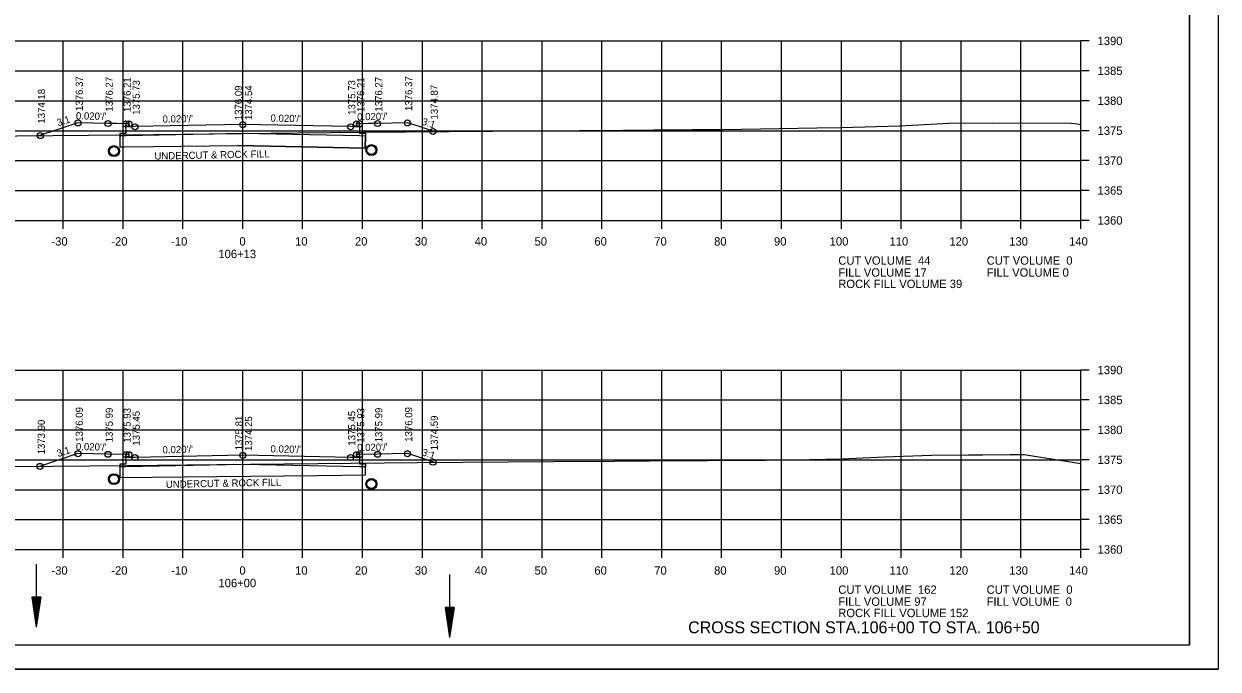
# Model space of a CAD drawing. Extents: x 1374311 to 1383814, y 384102 to 406278.
# Drawn here: x 1382684.3 to 1382883.8, y 385759.2 to 385867.1 of the extents above; entities that cross this region are included whole.
import ezdxf

# ---------------------------------------------------------------- set-up
doc = ezdxf.new("R2010")
doc.units = 0
for name, color, linetype in [('R_Axis', 7, 'Continuous'), ('R_Axis Annot', 7, 'Continuous'), ('R_Border', 7, 'Continuous'), ('R_Draft', 7, 'Continuous'), ('R_Exist Surface', 7, 'Continuous'), ('R_Fin Surface', 7, 'Continuous'), ('R_Grid', 7, 'Continuous'), ('R_No Plot', 7, 'Continuous'), ('R_Water', 7, 'Continuous'), ('R_Xsect Elev', 7, 'Continuous'), ('R_Xsect Slope', 7, 'Continuous')]:
    doc.layers.add(name, color=color, linetype=linetype)

msp = doc.modelspace()

# ---------------------------------------------------------------- linework, layer by layer
at = {"layer": 'R_Axis'}
for p, q in [((1382860.86, 385834.23), (1382860.86, 385864.23)), ((1382862.26, 385864.23), (1382860.86, 385864.23)), ((1382862.26, 385859.23), (1382860.86, 385859.23)), ((1382862.26, 385854.23), (1382860.86, 385854.23)), ((1382862.26, 385849.23), (1382860.86, 385849.23)), ((1382862.26, 385844.23), (1382860.86, 385844.23)), ((1382862.26, 385839.23), (1382860.86, 385839.23)), ((1382580.86, 385834.23), (1382860.86, 385834.23)), ((1382690.86, 385832.83), (1382690.86, 385834.23)), ((1382700.86, 385832.83), (1382700.86, 385834.23)), ((1382710.86, 385832.83), (1382710.86, 385834.23)), ((1382720.86, 385832.83), (1382720.86, 385834.23)), ((1382730.86, 385832.83), (1382730.86, 385834.23)), ((1382740.86, 385832.83), (1382740.86, 385834.23)), ((1382750.86, 385832.83), (1382750.86, 385834.23)), ((1382760.86, 385832.83), (1382760.86, 385834.23)), ((1382770.86, 385832.83), (1382770.86, 385834.23)), ((1382780.86, 385832.83), (1382780.86, 385834.23)), ((1382790.86, 385832.83), (1382790.86, 385834.23)), ((1382800.86, 385832.83), (1382800.86, 385834.23)), ((1382810.86, 385832.83), (1382810.86, 385834.23)), ((1382820.86, 385832.83), (1382820.86, 385834.23)), ((1382830.86, 385832.83), (1382830.86, 385834.23)), ((1382840.86, 385832.83), (1382840.86, 385834.23)), ((1382850.86, 385832.83), (1382850.86, 385834.23)), ((1382860.86, 385832.83), (1382860.86, 385834.23)), ((1382862.26, 385834.23), (1382860.86, 385834.23)), ((1382860.86, 385779.23), (1382860.86, 385809.23)), ((1382862.26, 385809.23), (1382860.86, 385809.23)), ((1382862.26, 385804.23), (1382860.86, 385804.23)), ((1382862.26, 385799.23), (1382860.86, 385799.23)), ((1382862.26, 385794.23), (1382860.86, 385794.23)), ((1382862.26, 385789.23), (1382860.86, 385789.23)), ((1382862.26, 385784.23), (1382860.86, 385784.23)), ((1382580.86, 385779.23), (1382860.86, 385779.23)), ((1382690.86, 385777.83), (1382690.86, 385779.23)), ((1382700.86, 385777.83), (1382700.86, 385779.23)), ((1382710.86, 385777.83), (1382710.86, 385779.23)), ((1382720.86, 385777.83), (1382720.86, 385779.23)), ((1382730.86, 385777.83), (1382730.86, 385779.23)), ((1382740.86, 385777.83), (1382740.86, 385779.23)), ((1382750.86, 385777.83), (1382750.86, 385779.23)), ((1382760.86, 385777.83), (1382760.86, 385779.23)), ((1382770.86, 385777.83), (1382770.86, 385779.23)), ((1382780.86, 385777.83), (1382780.86, 385779.23)), ((1382790.86, 385777.83), (1382790.86, 385779.23)), ((1382800.86, 385777.83), (1382800.86, 385779.23)), ((1382810.86, 385777.83), (1382810.86, 385779.23)), ((1382820.86, 385777.83), (1382820.86, 385779.23)), ((1382830.86, 385777.83), (1382830.86, 385779.23)), ((1382840.86, 385777.83), (1382840.86, 385779.23)), ((1382850.86, 385777.83), (1382850.86, 385779.23)), ((1382860.86, 385777.83), (1382860.86, 385779.23)), ((1382862.26, 385779.23), (1382860.86, 385779.23))]:
    msp.add_line(p, q, dxfattribs=at)
at = {"layer": 'R_Border'}
for q in [(1382879.04, 385968.69), (1382562.86, 385763.23)]:
    msp.add_line((1382879.04, 385763.23), q, dxfattribs=at)
at = {"layer": 'R_Draft'}
for p, q in [((1382685.61, 385771.28), (1382686.36, 385766.28)), ((1382687.11, 385771.28), (1382685.61, 385771.28)), ((1382685.74, 385771.28), (1382686.36, 385767.11)), ((1382685.86, 385771.28), (1382686.36, 385767.97)), ((1382685.99, 385771.28), (1382686.36, 385768.8)), ((1382686.12, 385771.28), (1382686.36, 385769.65)), ((1382686.24, 385771.28), (1382686.36, 385770.49)), ((1382687.11, 385771.28), (1382686.36, 385766.28)), ((1382686.6, 385771.28), (1382686.36, 385769.65)), ((1382686.86, 385771.28), (1382686.36, 385767.97)), ((1382686.99, 385771.28), (1382686.36, 385767.11)), ((1382686.73, 385771.28), (1382686.36, 385768.8)), ((1382686.48, 385771.28), (1382686.36, 385770.49)), ((1382754.66, 385769.54), (1382755.41, 385764.54)), ((1382756.16, 385769.54), (1382754.66, 385769.54)), ((1382754.78, 385769.54), (1382755.41, 385765.38)), ((1382754.91, 385769.54), (1382755.41, 385766.24)), ((1382755.04, 385769.54), (1382755.41, 385767.07)), ((1382755.16, 385769.54), (1382755.41, 385767.92)), ((1382755.29, 385769.54), (1382755.41, 385768.75)), ((1382756.16, 385769.54), (1382755.41, 385764.54)), ((1382755.65, 385769.54), (1382755.41, 385767.92)), ((1382755.91, 385769.54), (1382755.41, 385766.24)), ((1382756.03, 385769.54), (1382755.41, 385765.38)), ((1382755.78, 385769.54), (1382755.41, 385767.07)), ((1382755.53, 385769.54), (1382755.41, 385768.75))]:
    msp.add_line(p, q, dxfattribs=at)
at = {"layer": 'R_Exist Surface'}
for points in [[(1382677.08, 385848.33), (1382701.06, 385848.53), (1382720.96, 385848.77), (1382730.1, 385848.86), (1382740.85, 385849), (1382762.57, 385849.17), (1382784.41, 385849.31), (1382789.54, 385849.38), (1382795.91, 385849.42), (1382801.03, 385849.45), (1382816.76, 385849.71), (1382820.69, 385849.78), (1382824.81, 385849.88), (1382826.68, 385849.92), (1382830.64, 385850.05), (1382838.86, 385850.46), (1382846.16, 385850.55), (1382859.29, 385850.51), (1382860.26, 385850.36), (1382860.86, 385850.25)], [(1382669.83, 385793.07), (1382689.09, 385793.14), (1382701.54, 385793.3), (1382716.53, 385793.42), (1382733.38, 385793.62), (1382750.07, 385793.8), (1382772.78, 385793.93), (1382782.93, 385794.01), (1382786.77, 385794.04), (1382787.67, 385794.05), (1382788.79, 385794.06), (1382808.24, 385794.17), (1382815.61, 385794.29), (1382820.91, 385794.39), (1382828.06, 385794.73), (1382835.93, 385795), (1382842.02, 385795.05), (1382844.47, 385795.05), (1382849.06, 385795.1), (1382851.41, 385795.1), (1382860.86, 385793.62)]]:
    msp.add_lwpolyline(points, dxfattribs=at)
for centre in [(1382699.35, 385845.81), (1382742.36, 385845.98), (1382699.35, 385790.99), (1382742.36, 385790.19)]:
    msp.add_circle(centre, 0.917, dxfattribs=at)
at = {"layer": 'R_Fin Surface'}
for p, q in [((1382741.33, 385846.33), (1382741.37, 385848.33)), ((1382720.04, 385846.75), (1382741.33, 385846.33))]:
    msp.add_line(p, q, dxfattribs=at)
for points in [[(1382686.78, 385848.41), (1382690, 385849.48), (1382693.35, 385850.6), (1382695.8, 385850.55), (1382698.35, 385850.5), (1382699.82, 385850.47), (1382701.35, 385850.44), (1382701.6, 385850.44), (1382701.85, 385850.44), (1382701.86, 385850.18), (1382701.86, 385849.94), (1382702.37, 385849.95), (1382702.86, 385849.96), (1382711.68, 385850.14), (1382720.86, 385850.32), (1382729.68, 385850.14), (1382738.86, 385849.96), (1382739.35, 385849.95), (1382739.86, 385849.94), (1382739.87, 385850.19), (1382739.87, 385850.44), (1382740.12, 385850.44), (1382740.37, 385850.44), (1382741.84, 385850.47), (1382743.37, 385850.5), (1382745.82, 385850.55), (1382748.37, 385850.6), (1382750.58, 385849.86), (1382752.88, 385849.1)], [(1382740.37, 385850.36), (1382740.38, 385848.82), (1382741.38, 385848.83), (1382741.37, 385848.33), (1382740.37, 385848.35), (1382720.86, 385848.74), (1382701.35, 385848.35), (1382700.35, 385848.33), (1382700.36, 385848.83), (1382701.36, 385848.82), (1382701.35, 385850.36)], [(1382700.35, 385848.33), (1382700.31, 385846.52), (1382701.08, 385846.53), (1382720.04, 385846.75)], [(1382700.35, 385848.33), (1382700.31, 385846.52), (1382701.08, 385846.53), (1382720.04, 385846.75)], [(1382741.37, 385848.33), (1382740.37, 385848.35), (1382720.86, 385848.74), (1382701.35, 385848.35), (1382700.35, 385848.33)], [(1382741.37, 385848.33), (1382741.33, 385846.33), (1382720.04, 385846.75)], [(1382686.77, 385793.13), (1382693.35, 385795.32), (1382698.35, 385795.22), (1382701.35, 385795.16), (1382701.85, 385795.16), (1382701.86, 385794.66), (1382702.86, 385794.68), (1382720.86, 385795.04), (1382738.86, 385794.68), (1382739.86, 385794.66), (1382739.87, 385795.16), (1382740.37, 385795.16), (1382743.37, 385795.22), (1382748.37, 385795.32), (1382752.87, 385793.82)], [(1382740.37, 385795.08), (1382740.38, 385793.55), (1382741.38, 385793.55), (1382741.37, 385793.05), (1382740.37, 385793.07), (1382720.86, 385793.46), (1382701.35, 385793.07), (1382700.35, 385793.05), (1382700.36, 385793.55), (1382701.36, 385793.55), (1382701.35, 385795.08)], [(1382700.35, 385793.05), (1382700.32, 385791.29), (1382716.55, 385791.42), (1382733.4, 385791.62), (1382741.34, 385791.71), (1382741.37, 385793.05)], [(1382700.35, 385793.05), (1382700.32, 385791.29), (1382716.55, 385791.42), (1382733.4, 385791.62), (1382741.34, 385791.71), (1382741.37, 385793.05)], [(1382741.37, 385793.05), (1382740.37, 385793.07), (1382720.86, 385793.46), (1382701.35, 385793.07), (1382700.35, 385793.05)]]:
    msp.add_lwpolyline(points, dxfattribs=at)
at = {"layer": 'R_Grid'}
for p, q in [((1382580.86, 385864.23), (1382860.86, 385864.23)), ((1382690.86, 385834.23), (1382690.86, 385864.23)), ((1382700.86, 385834.23), (1382700.86, 385864.23)), ((1382710.86, 385834.23), (1382710.86, 385864.23)), ((1382720.86, 385834.23), (1382720.86, 385864.23)), ((1382730.86, 385834.23), (1382730.86, 385864.23)), ((1382740.86, 385834.23), (1382740.86, 385864.23)), ((1382750.86, 385834.23), (1382750.86, 385864.23)), ((1382760.86, 385834.23), (1382760.86, 385864.23)), ((1382770.86, 385834.23), (1382770.86, 385864.23)), ((1382780.86, 385834.23), (1382780.86, 385864.23)), ((1382790.86, 385834.23), (1382790.86, 385864.23)), ((1382800.86, 385834.23), (1382800.86, 385864.23)), ((1382810.86, 385834.23), (1382810.86, 385864.23)), ((1382820.86, 385834.23), (1382820.86, 385864.23)), ((1382830.86, 385834.23), (1382830.86, 385864.23)), ((1382840.86, 385834.23), (1382840.86, 385864.23)), ((1382850.86, 385834.23), (1382850.86, 385864.23)), ((1382860.86, 385834.23), (1382860.86, 385864.23)), ((1382580.86, 385859.23), (1382860.86, 385859.23)), ((1382580.86, 385854.23), (1382860.86, 385854.23)), ((1382580.86, 385849.23), (1382860.86, 385849.23)), ((1382580.86, 385844.23), (1382860.86, 385844.23)), ((1382580.86, 385839.23), (1382860.86, 385839.23)), ((1382580.86, 385834.23), (1382860.86, 385834.23)), ((1382580.86, 385809.23), (1382860.86, 385809.23)), ((1382690.86, 385779.23), (1382690.86, 385809.23)), ((1382700.86, 385779.23), (1382700.86, 385809.23)), ((1382710.86, 385779.23), (1382710.86, 385809.23)), ((1382720.86, 385779.23), (1382720.86, 385809.23)), ((1382730.86, 385779.23), (1382730.86, 385809.23)), ((1382740.86, 385779.23), (1382740.86, 385809.23)), ((1382750.86, 385779.23), (1382750.86, 385809.23)), ((1382760.86, 385779.23), (1382760.86, 385809.23)), ((1382770.86, 385779.23), (1382770.86, 385809.23)), ((1382780.86, 385779.23), (1382780.86, 385809.23)), ((1382790.86, 385779.23), (1382790.86, 385809.23)), ((1382800.86, 385779.23), (1382800.86, 385809.23)), ((1382810.86, 385779.23), (1382810.86, 385809.23)), ((1382820.86, 385779.23), (1382820.86, 385809.23)), ((1382830.86, 385779.23), (1382830.86, 385809.23)), ((1382840.86, 385779.23), (1382840.86, 385809.23)), ((1382850.86, 385779.23), (1382850.86, 385809.23)), ((1382860.86, 385779.23), (1382860.86, 385809.23)), ((1382580.86, 385804.23), (1382860.86, 385804.23)), ((1382580.86, 385799.23), (1382860.86, 385799.23)), ((1382580.86, 385794.23), (1382860.86, 385794.23)), ((1382580.86, 385789.23), (1382860.86, 385789.23)), ((1382580.86, 385784.23), (1382860.86, 385784.23)), ((1382580.86, 385779.23), (1382860.86, 385779.23))]:
    msp.add_line(p, q, dxfattribs=at)
at = {"layer": 'R_No Plot'}
msp.add_line((1382550.46, 385759.25), (1382883.79, 385759.25), dxfattribs=at)
for points in [[(1382550.45, 385972.58), (1382883.79, 385972.58), (1382883.79, 385759.24), (1382550.45, 385759.24)], [(1382796.78, 385968.69), (1382796.78, 385958.81), (1382832.51, 385958.81), (1382832.51, 385955.89), (1382855.71, 385955.89), (1382855.71, 385932.67), (1382879.04, 385932.67), (1382879.04, 385763.23), (1382562.86, 385763.23), (1382562.86, 385968.69)]]:
    msp.add_lwpolyline(points, close=True, dxfattribs=at)
for centre in [(1382693.35, 385850.52), (1382698.35, 385850.42), (1382701.35, 385850.36), (1382701.85, 385850.36), (1382702.86, 385849.88), (1382720.86, 385850.24), (1382738.86, 385849.88), (1382739.87, 385850.36), (1382740.37, 385850.36), (1382743.37, 385850.42), (1382748.37, 385850.52), (1382752.64, 385849.09), (1382687.03, 385848.41), (1382687.03, 385848.41), (1382693.35, 385795.24), (1382698.35, 385795.14), (1382701.35, 385795.08), (1382701.85, 385795.08), (1382739.87, 385795.08), (1382740.37, 385795.08), (1382743.37, 385795.14), (1382748.37, 385795.24), (1382687, 385793.13), (1382687, 385793.13), (1382702.86, 385794.6), (1382720.86, 385794.96), (1382738.86, 385794.6), (1382752.65, 385793.82)]:
    msp.add_circle(centre, 0.5, dxfattribs=at)
at = {"layer": 'R_Water'}
for p, q in [((1382686.36, 385776.78), (1382686.36, 385766.28)), ((1382755.41, 385775.05), (1382755.41, 385764.54))]:
    msp.add_line(p, q, dxfattribs=at)
for centre in [(1382699.35, 385845.81), (1382742.36, 385845.98), (1382699.35, 385790.99), (1382742.36, 385790.19)]:
    msp.add_circle(centre, 0.75, dxfattribs=at)

# ---------------------------------------------------------------- texts
at = {"layer": 'R_Axis Annot'}
for s, p in [('1390', (1382863.66, 385863.53)), ('1385', (1382863.66, 385858.53)), ('1380', (1382863.66, 385853.53)), ('1375', (1382863.66, 385848.53)), ('1370', (1382863.66, 385843.53)), ('1365', (1382863.66, 385838.53)), ('1360', (1382863.66, 385833.53)), ('-30', (1382688.9, 385830.03)), ('-20', (1382698.9, 385830.03)), ('-10', (1382708.9, 385830.03)), ('0', (1382720.3, 385830.03)), ('10', (1382729.6, 385830.03)), ('20', (1382739.6, 385830.03)), ('30', (1382749.6, 385830.03)), ('40', (1382759.6, 385830.03)), ('50', (1382769.6, 385830.03)), ('60', (1382779.6, 385830.03)), ('70', (1382789.6, 385830.03)), ('80', (1382799.6, 385830.03)), ('90', (1382809.6, 385830.03)), ('100', (1382818.9, 385830.03)), ('110', (1382828.9, 385830.03)), ('120', (1382838.9, 385830.03)), ('130', (1382848.9, 385830.03)), ('140', (1382858.9, 385830.03)), ('106+13', (1382716.79, 385827.93)), ('CUT VOLUME  44', (1382820.34, 385826.83)), ('CUT VOLUME  0', (1382845.12, 385826.83)), ('FILL VOLUME 17', (1382820.34, 385824.83)), ('FILL VOLUME 0', (1382845.12, 385824.83)), ('ROCK FILL VOLUME 39', (1382820.34, 385822.93)), ('1390', (1382863.66, 385808.53)), ('1385', (1382863.66, 385803.53)), ('1380', (1382863.66, 385798.53)), ('1375', (1382863.66, 385793.53)), ('1370', (1382863.66, 385788.53)), ('1365', (1382863.66, 385783.53)), ('1360', (1382863.66, 385778.53)), ('-30', (1382688.9, 385775.03)), ('-20', (1382698.9, 385775.03)), ('-10', (1382708.9, 385775.03)), ('0', (1382720.3, 385775.03)), ('10', (1382729.6, 385775.03)), ('20', (1382739.6, 385775.03)), ('30', (1382749.6, 385775.03)), ('40', (1382759.6, 385775.03)), ('50', (1382769.6, 385775.03)), ('60', (1382779.6, 385775.03)), ('70', (1382789.6, 385775.03)), ('80', (1382799.6, 385775.03)), ('90', (1382809.6, 385775.03)), ('100', (1382818.9, 385775.03)), ('110', (1382828.9, 385775.03)), ('120', (1382838.9, 385775.03)), ('130', (1382848.9, 385775.03)), ('140', (1382858.9, 385775.03)), ('106+00', (1382716.8, 385772.93)), ('CUT VOLUME  162', (1382820.34, 385771.83)), ('CUT VOLUME  0', (1382845.12, 385771.83)), ('FILL VOLUME 97', (1382820.34, 385769.83)), ('FILL VOLUME  0', (1382845.12, 385769.83)), ('ROCK FILL VOLUME 152', (1382820.34, 385767.93))]:
    msp.add_text(s, height=1.4, dxfattribs=at).set_placement(p)
at = {"layer": 'R_Draft'}
msp.add_text('CROSS SECTION STA.106+00 TO STA. 106+50', height=2, dxfattribs=at).set_placement((1382795.26, 385765.23))
at = {"layer": 'R_Fin Surface'}
for p in [(1382706.12, 385844.39), (1382708.03, 385789.52)]:
    msp.add_text('UNDERCUT & ROCK FILL', height=1.2, rotation=1.1458, dxfattribs=at).set_placement(p)
at = {"layer": 'R_Xsect Elev'}
for s, p in [('1376.37', (1382694.15, 385852.52)), ('1376.27', (1382699.15, 385852.42)), ('1376.21', (1382702.15, 385852.36)), ('1375.73', (1382703.66, 385851.88)), ('1375.73', (1382739.66, 385851.88)), ('1376.21', (1382741.17, 385852.36)), ('1376.27', (1382744.17, 385852.42)), ('1376.37', (1382749.17, 385852.52)), ('1374.18', (1382687.83, 385850.41)), ('1376.09', (1382720.73, 385850.99)), ('1374.54', (1382722.43, 385851)), ('1374.87', (1382753.44, 385851.09)), ('1376.09', (1382694.15, 385797.24)), ('1375.99', (1382699.15, 385797.14)), ('1375.93', (1382702.15, 385797.08)), ('1375.45', (1382703.66, 385796.6)), ('1375.45', (1382739.66, 385796.6)), ('1375.93', (1382741.17, 385797.08)), ('1375.99', (1382744.17, 385797.14)), ('1376.09', (1382749.17, 385797.24)), ('1374.59', (1382753.45, 385795.82)), ('1373.90', (1382687.8, 385795.13)), ('1375.81', (1382720.82, 385795.8)), ('1374.25', (1382722.43, 385795.7))]:
    msp.add_text(s, height=1.2, rotation=90, dxfattribs=at).set_placement(p)
at = {"layer": 'R_Xsect Slope'}
for s, rotation, p in [('3:1', 18.4349, (1382690.03, 385849.94)), ("0.020'/'", 358.8542, (1382692.98, 385851.13)), ("0.020'/'", 1.1458, (1382707.47, 385850.57)), ("0.020'/'", 358.8542, (1382725.49, 385850.75)), ("0.020'/'", 1.1458, (1382739.98, 385850.95)), ('3:1', 341.5651, (1382750.67, 385850.28)), ('3:1', 18.4349, (1382690.02, 385794.66)), ("0.020'/'", 358.8542, (1382692.98, 385795.85)), ("0.020'/'", 1.1458, (1382707.47, 385795.3)), ("0.020'/'", 358.8542, (1382725.49, 385795.47)), ("0.020'/'", 1.1458, (1382739.98, 385795.68)), ('3:1', 341.5651, (1382750.67, 385795.01))]:
    msp.add_text(s, height=1.2, rotation=rotation, dxfattribs=at).set_placement(p)

doc.saveas('drawing.dxf')
